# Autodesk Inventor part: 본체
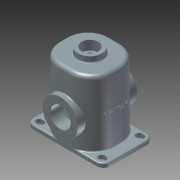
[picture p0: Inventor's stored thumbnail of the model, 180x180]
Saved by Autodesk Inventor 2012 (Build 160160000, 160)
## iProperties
Company: 한국ATC센터
Created: 2014-10
Part Number: 본체
Document SubType Name: Modeling
Designer: 한국ATC센터
Density: 2.71 g/cm^3
Material: 용접된 알루미늄-6061
Mass: 2951.76 g
Surface Area: 2149.68 cm^2
Volume: 1089.21 cm^3
Author: KYOUNG IL JANG
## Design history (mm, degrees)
sketch "스케치1"
  geometry: L1 (-70, 65)-(70, 65); L2 (70, 65)-(70, -65); L3 (70, -65)-(-70, -65); L4 (-70, -65)-(-70, 65); 3 further points
  constraints: 8 end point, 2 midpoint, 2 parallel, 1 horizontal, 1 horizontal alignment, 1 perpendicular, 1 vertical alignment
  dimensions: "d0" = 140 distance of L2.end L3.end; "d68" = 130 distance of L3.end L1.start
extrude "돌출1" new body sketch "스케치1" distance "d1" = 180; taper "d2" = 0 deg
fillet "모깎기1" dims "d3" = 55
feature "쉘1" dims "d4" = 10
sketch "스케치2"
  geometry: L1 (-70, 10)-(-70, -10) reference; L2 (-15, -65)-(-82, -65); L3 (-82, 65)-(-15, 65); L4 (-83, 57)-(-78, 57); L5 (-78, 41)-(-83, 41); L6 (-100, 47)-(-100, -47); A1 r 55 centre (-15, 10) between (-15, 65) and (-70, 10) reference; A2 r 55 centre (-15, -10) between (-70, -10) and (-15, -65) reference; A3 r 8 centre (-78, 49) between (-78, 41) and (-78, 57); A4 r 8 centre (-83, 49) between (-83, 57) and (-83, 41); A5 r 18 centre (-82, 47) between (-82, 65) and (-100, 47); A6 r 18 centre (-82, -47) between (-100, -47) and (-82, -65); 1 further point
  constraints: 10 end point, 9 tangent, 8 point on circle, 4 centre point, 2 parallel, 2 perpendicular, 1 equal radius
  dimensions: "d6" = 49 vertical distance of point (0, 0) A3.centre; "d8" = 16 distance between parallel lines of L4 L5; "d64" = 18 radius of A5; "d65" = 8 distance from line of A3.centre L1; "d66" = 30 distance between parallel lines of L6 L1; "d67" = 5 distance of A4.centre A3.centre
extrude "돌출2" join sketch "스케치2" distance "d9" = 10; taper "d10" = 0 deg
extrude "돌출3" cut sketch "스케치2" stored distance "d11" = 10; taper "d12" = 0 deg
sketch "스케치3"
  geometry: L1 (-65, 10)-(-65, 180) reference; L2 (-55, 0)-(-55, 170) reference; L3 (-77, 75)-(-45, 75); L4 (10, 0)-(-10, 0) reference; L5 (-77, 75)-(-77, 120.5); L6 (-77, 120.5)-(-55, 120.5); L7 (-55, 120.5)-(-45, 110.5); L8 (-45, 110.5)-(-45, 75); 3 further points
  constraints: 10 end point, 4 perpendicular, 1 point on line
  dimensions: "d13" = 75 distance between parallel lines of L3 L4; "d14" = 12 distance from line of L1 L3.start; "d15" = 10 distance from line of L3.end L2; "d16" = 91 diameter of L6 L3; "d17" = 135 deg angle of L7 L2
revolve "회전1" sketch "스케치3" stored, may be unused: angle "d18" = 90 deg
sketch "스케치4"
  geometry: C1 r 45.5 at (0, 0) reference; 2 further points
  constraints: 1 vertical alignment
  dimensions: "d19" = 35 distance of C1.centre point (0, 35)
hole "구멍1" sketch "스케치4" at (0, 35) diameter "d20" = 3.459; stored, may be unused: countersink angle "d24" = 90 deg, drill point angle "d26" = 118 deg; dims "d21" = 13, "d22" = 4, "d23" = 2, "d25" = 16
fillet "모깎기2" dims "d30" = 3
hole "구멍2" diameter "d33" = 52; stored, may be unused: countersink angle "d37" = 90 deg, drill point angle "d39" = 118 deg; dims "d31" = 10, "d32" = 10, "d34" = 13, "d35" = 4, "d36" = 2, "d38" = 16
sketch "스케치5"
  geometry: C1 r 31 at (0, 0); 1 further point
  constraints: 1 centre point, 1 coincident
  dimensions: "d40" = 62 diameter of C1
extrude "돌출4" join sketch "스케치5" distance "d41" = 15; taper "d42" = 0 deg
hole "구멍3" diameter "d45" = 43; stored, may be unused: countersink angle "d49" = 90 deg, drill point angle "d51" = 118 deg; dims "d43" = 10, "d44" = 10, "d46" = 13, "d47" = 4, "d48" = 2, "d50" = 16
fillet "모깎기3" dims "d52" = 3
fillet "모깎기4" dims "d53" = 3
chamfer "모따기1" distance "d55" = 1; stored, may be unused: second distance "d56" = 2, angle "d57" = 45 deg
sketch "스케치6"
  geometry: 2 further points
  constraints: 1 vertical alignment, 1 other
  dimensions: "d71" = 90 distance of point (0, 0) point (0, 90)
feature "엠보싱2" sketch "스케치6" dims "d0" = 140, "d68" = 130, "d72" = 1, "d73" = 0
fillet "모깎기6" dims "d74" = 10
sketch "스케치7"
  geometry: C1 r 15 at (0, 0); C2 r 21.5 at (0, 0) reference; C3 r 25 at (0, 0); 1 further point
  constraints: 2 centre point, 2 coincident
  dimensions: "d61" = 30 diameter of C1; "d75" = 50 diameter of C3
extrude "돌출5" join sketch "스케치7" distance "d62" = 10; taper "d63" = 0 deg
feature "면 이동1" dims "d76" = 1
node "솔리드1"
mirror "대칭1"
mirror "대칭2"
pattern_circular "원형 패턴1" dims angle "d28" = 360 deg
mirror "대칭3"
